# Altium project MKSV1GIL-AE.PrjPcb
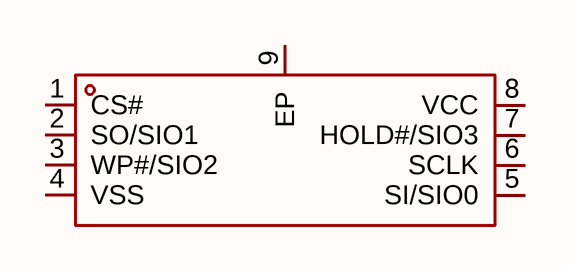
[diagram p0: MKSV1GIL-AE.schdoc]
1 sheet, 1 parts. Net scope: global (net labels, ports and power ports of the same name join across sheets).

## Sheet MKSV1GIL-AE.schdoc
size 127 x 101 mm

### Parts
U?  mksv1gil-ae  [WSON-8_L8.0-W6.0-P1.27-BL-EP-1]  (value not drawn)

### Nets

Not connected (* = marked no-connect by the designer): U? 1(CS#) 2(SO/SIO1) 3(WP#/SIO2) 4(VSS) 5(SI/SIO0) 6(SCLK) 7(HOLD#/SIO3) 8(VCC) 9(EP)

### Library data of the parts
U? = mksv1gil-ae: 存储容量:1Gbit;时钟频率(fc):104MHz;工作电压:2.7V~3.6V;; Manufacturer: MK(米客方德); AddInBom: yes; Memory Size: 1Gbit; Interface: SPI; Clock Frequency: 104MHz; Page Program time (TPP): 600us; Block Erase Time(tBE): 3ms; Data Retention - TDR (Year): 10年; Standby Supply Current: 65uA; Program / Erase Cycles: 10万次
